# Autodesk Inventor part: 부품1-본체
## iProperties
Created: 2015-01
Part Number: 부품1-본체
Document SubType Name: Modeling
Designer: Administrator
Density: 2.71 g/cm^3
Material: 알루미늄-6061
Mass: 1028.9 g
Surface Area: 1083.1 cm^2
Volume: 379.668 cm^3
Author: Administrator
